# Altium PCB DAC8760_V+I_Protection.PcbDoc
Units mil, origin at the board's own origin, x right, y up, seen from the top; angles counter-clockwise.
Board outline 3000 x 3000 mil, 4 copper layers (Top Layer, Mid-Layer 1, Mid-Layer 2, Bottom Layer); 47 components, 28 nets, 152 pads, 114 vias.
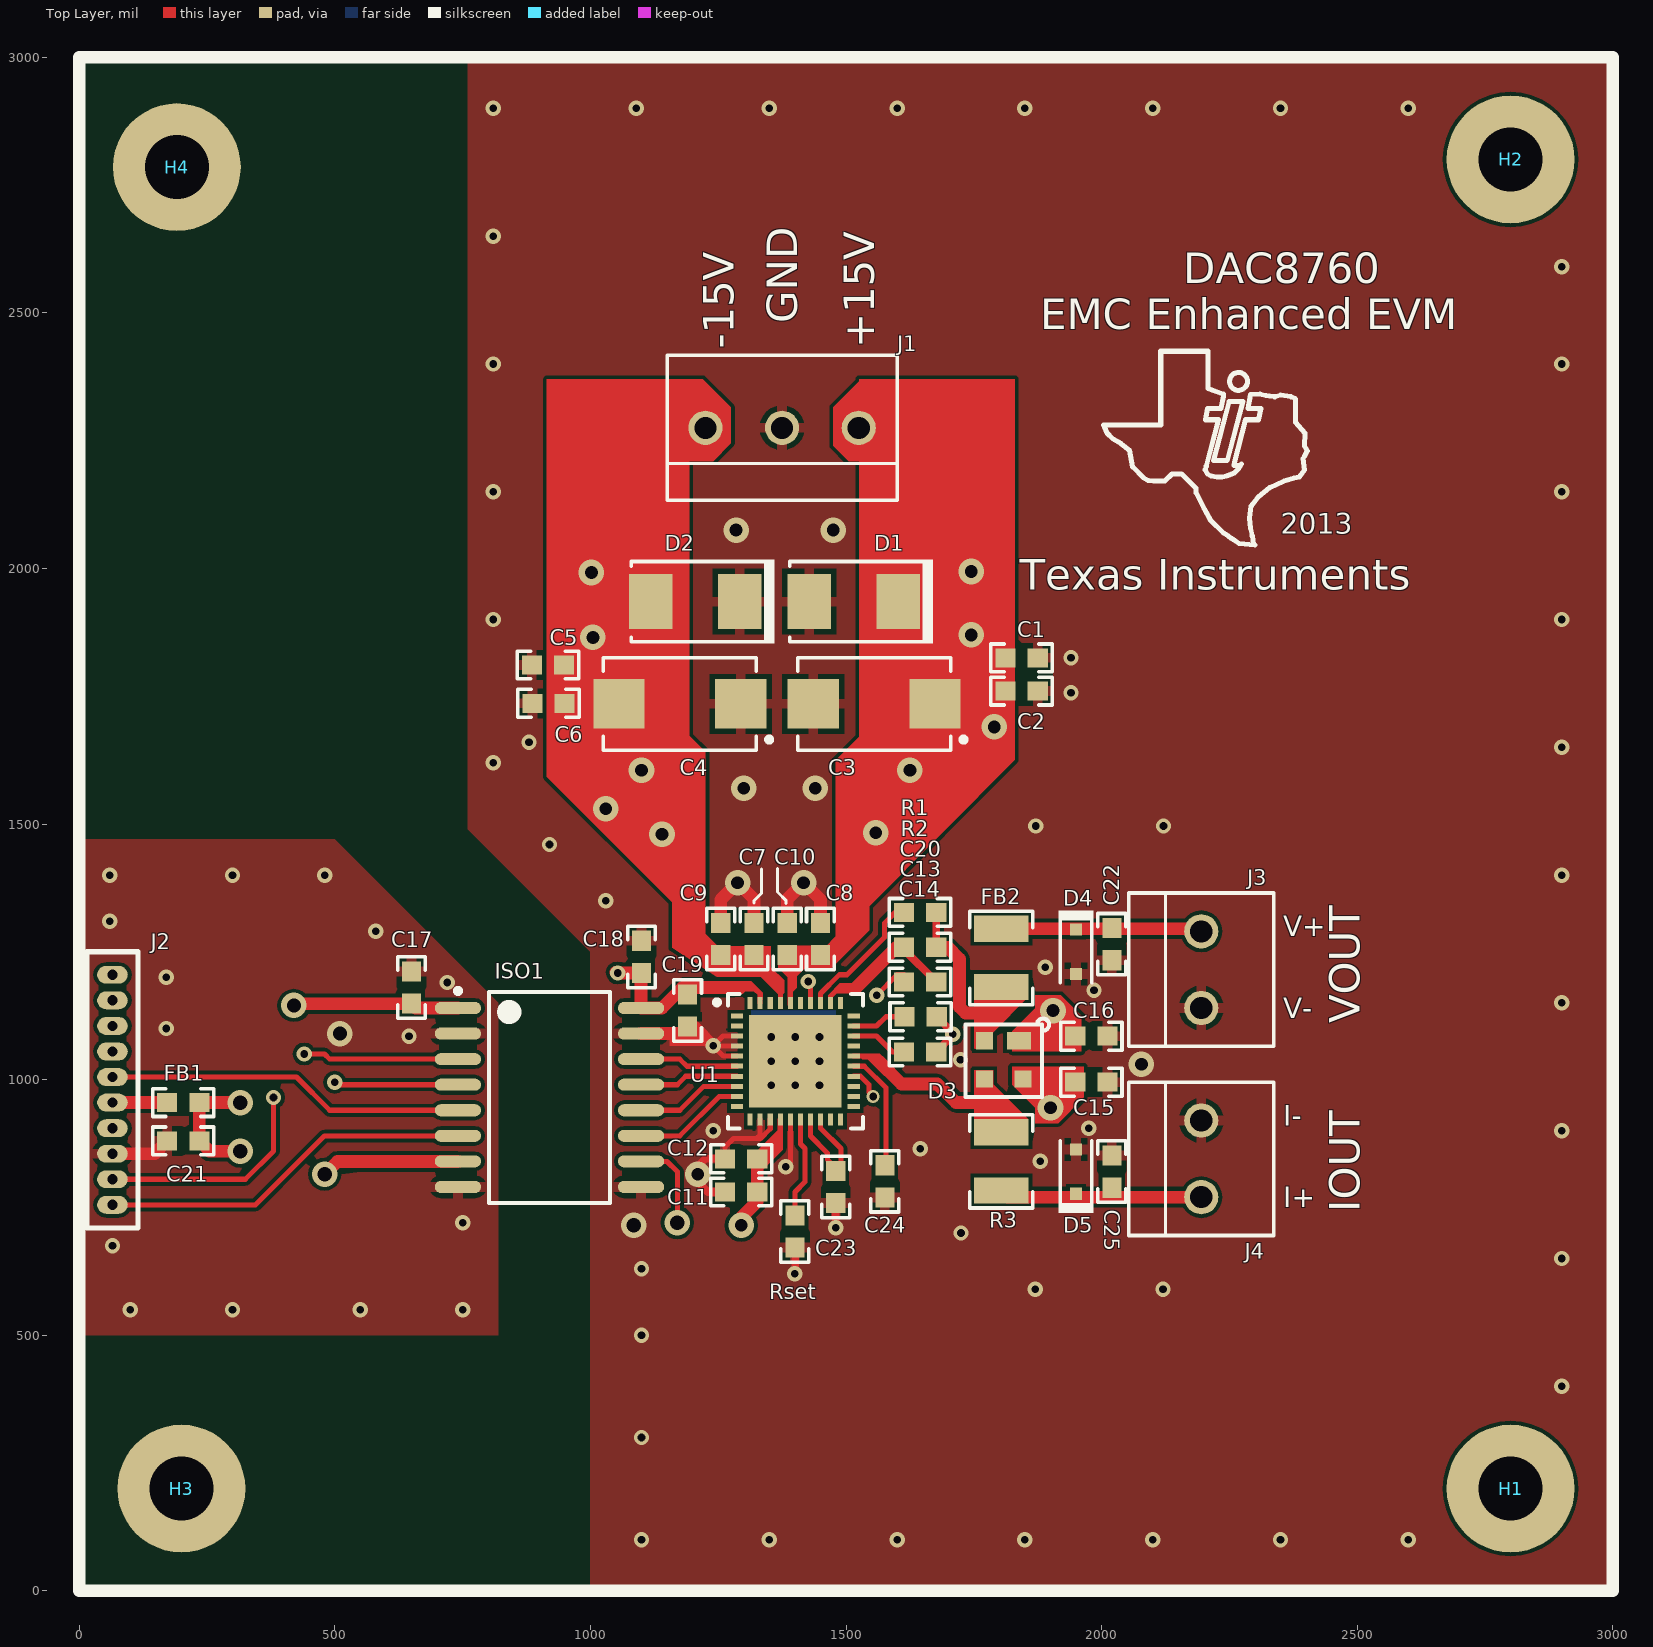
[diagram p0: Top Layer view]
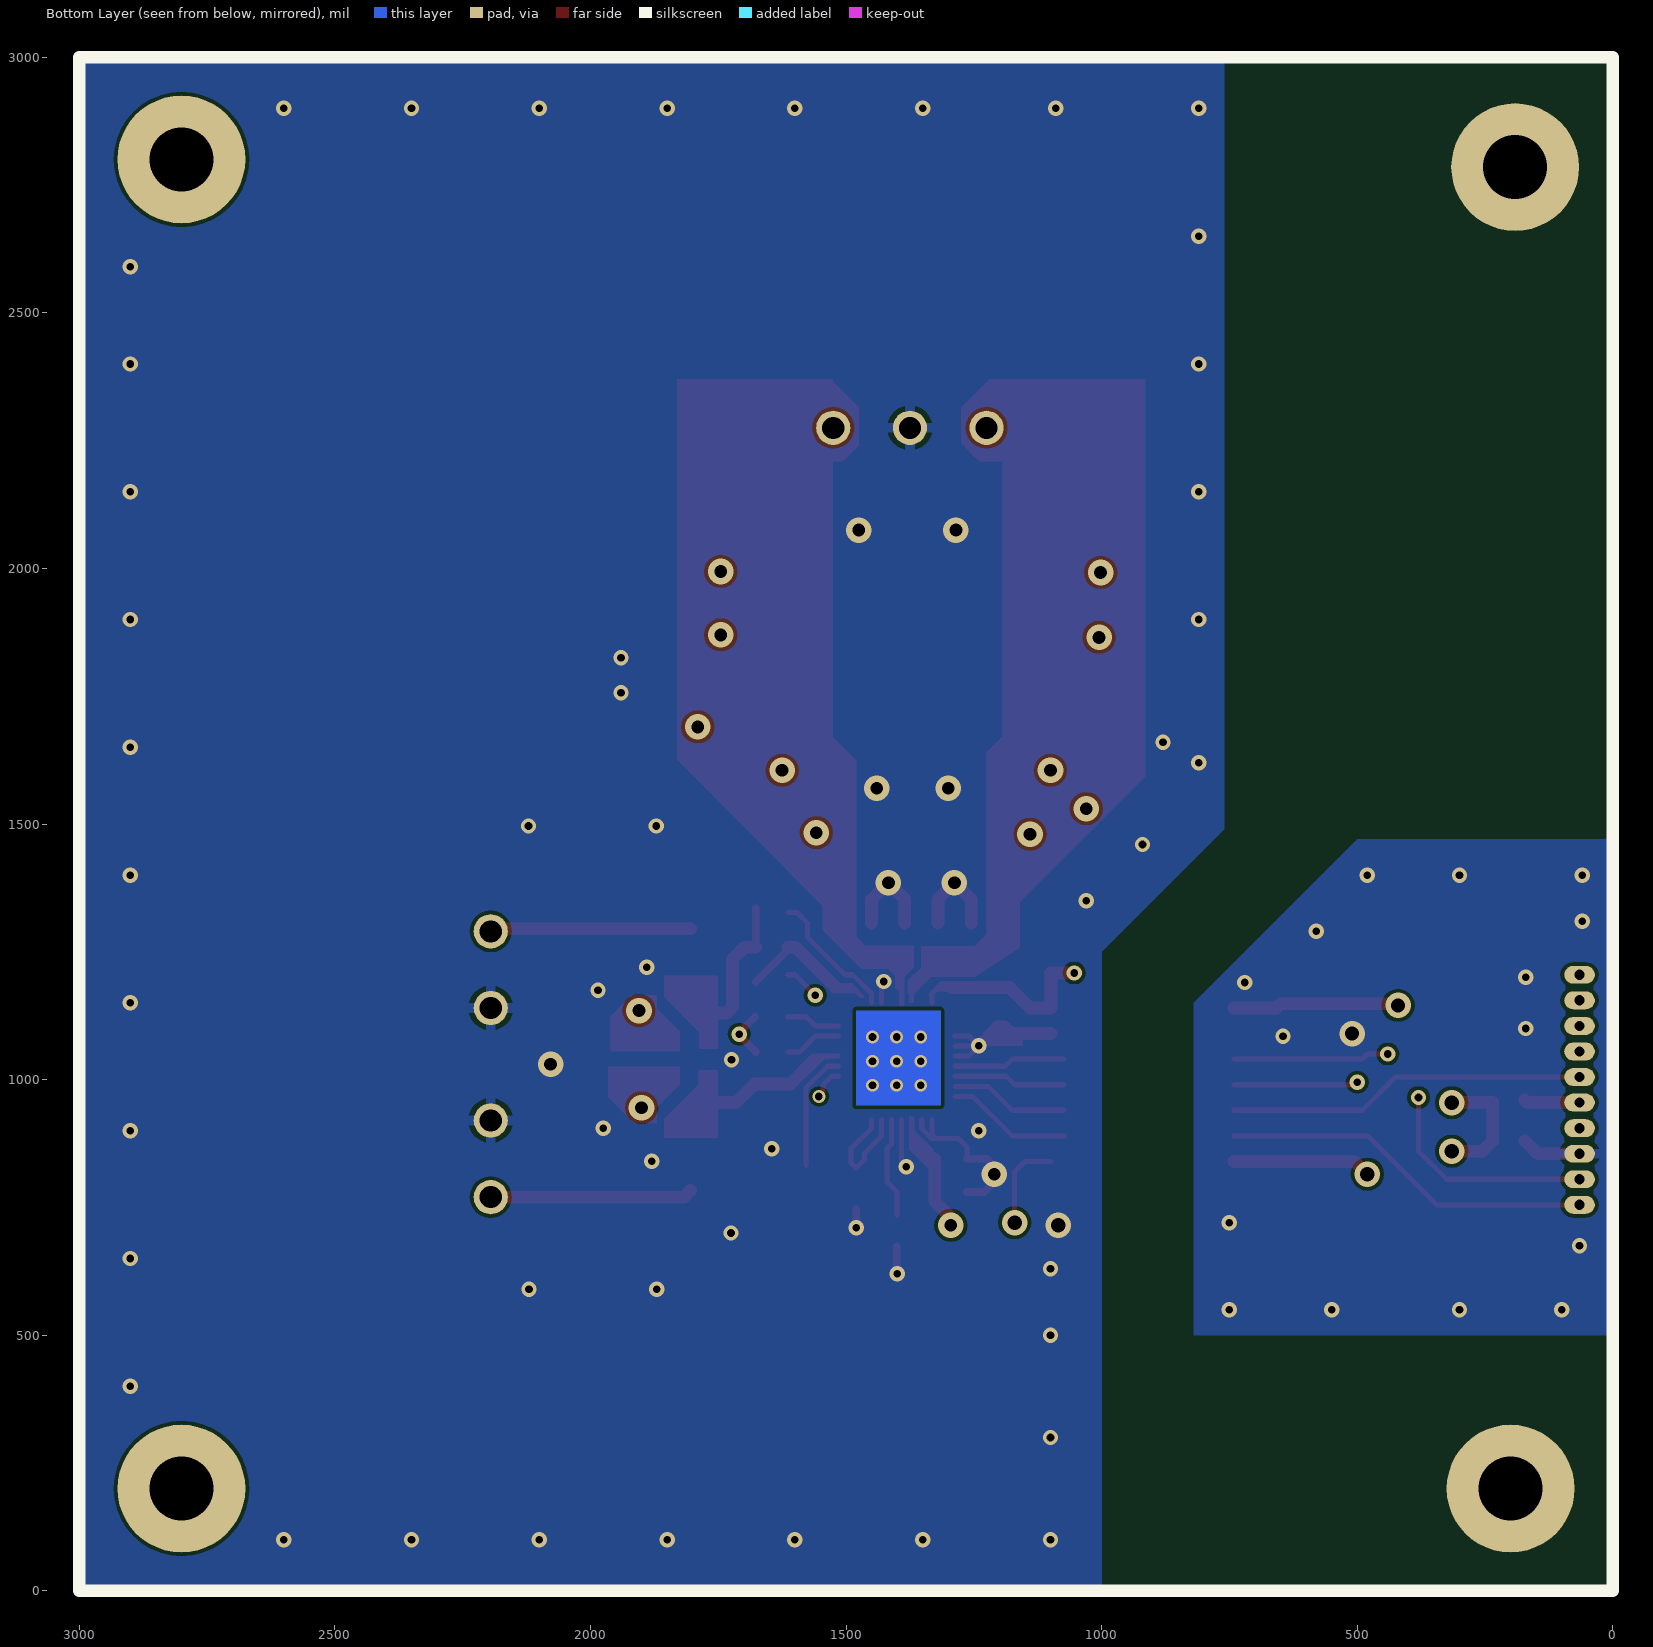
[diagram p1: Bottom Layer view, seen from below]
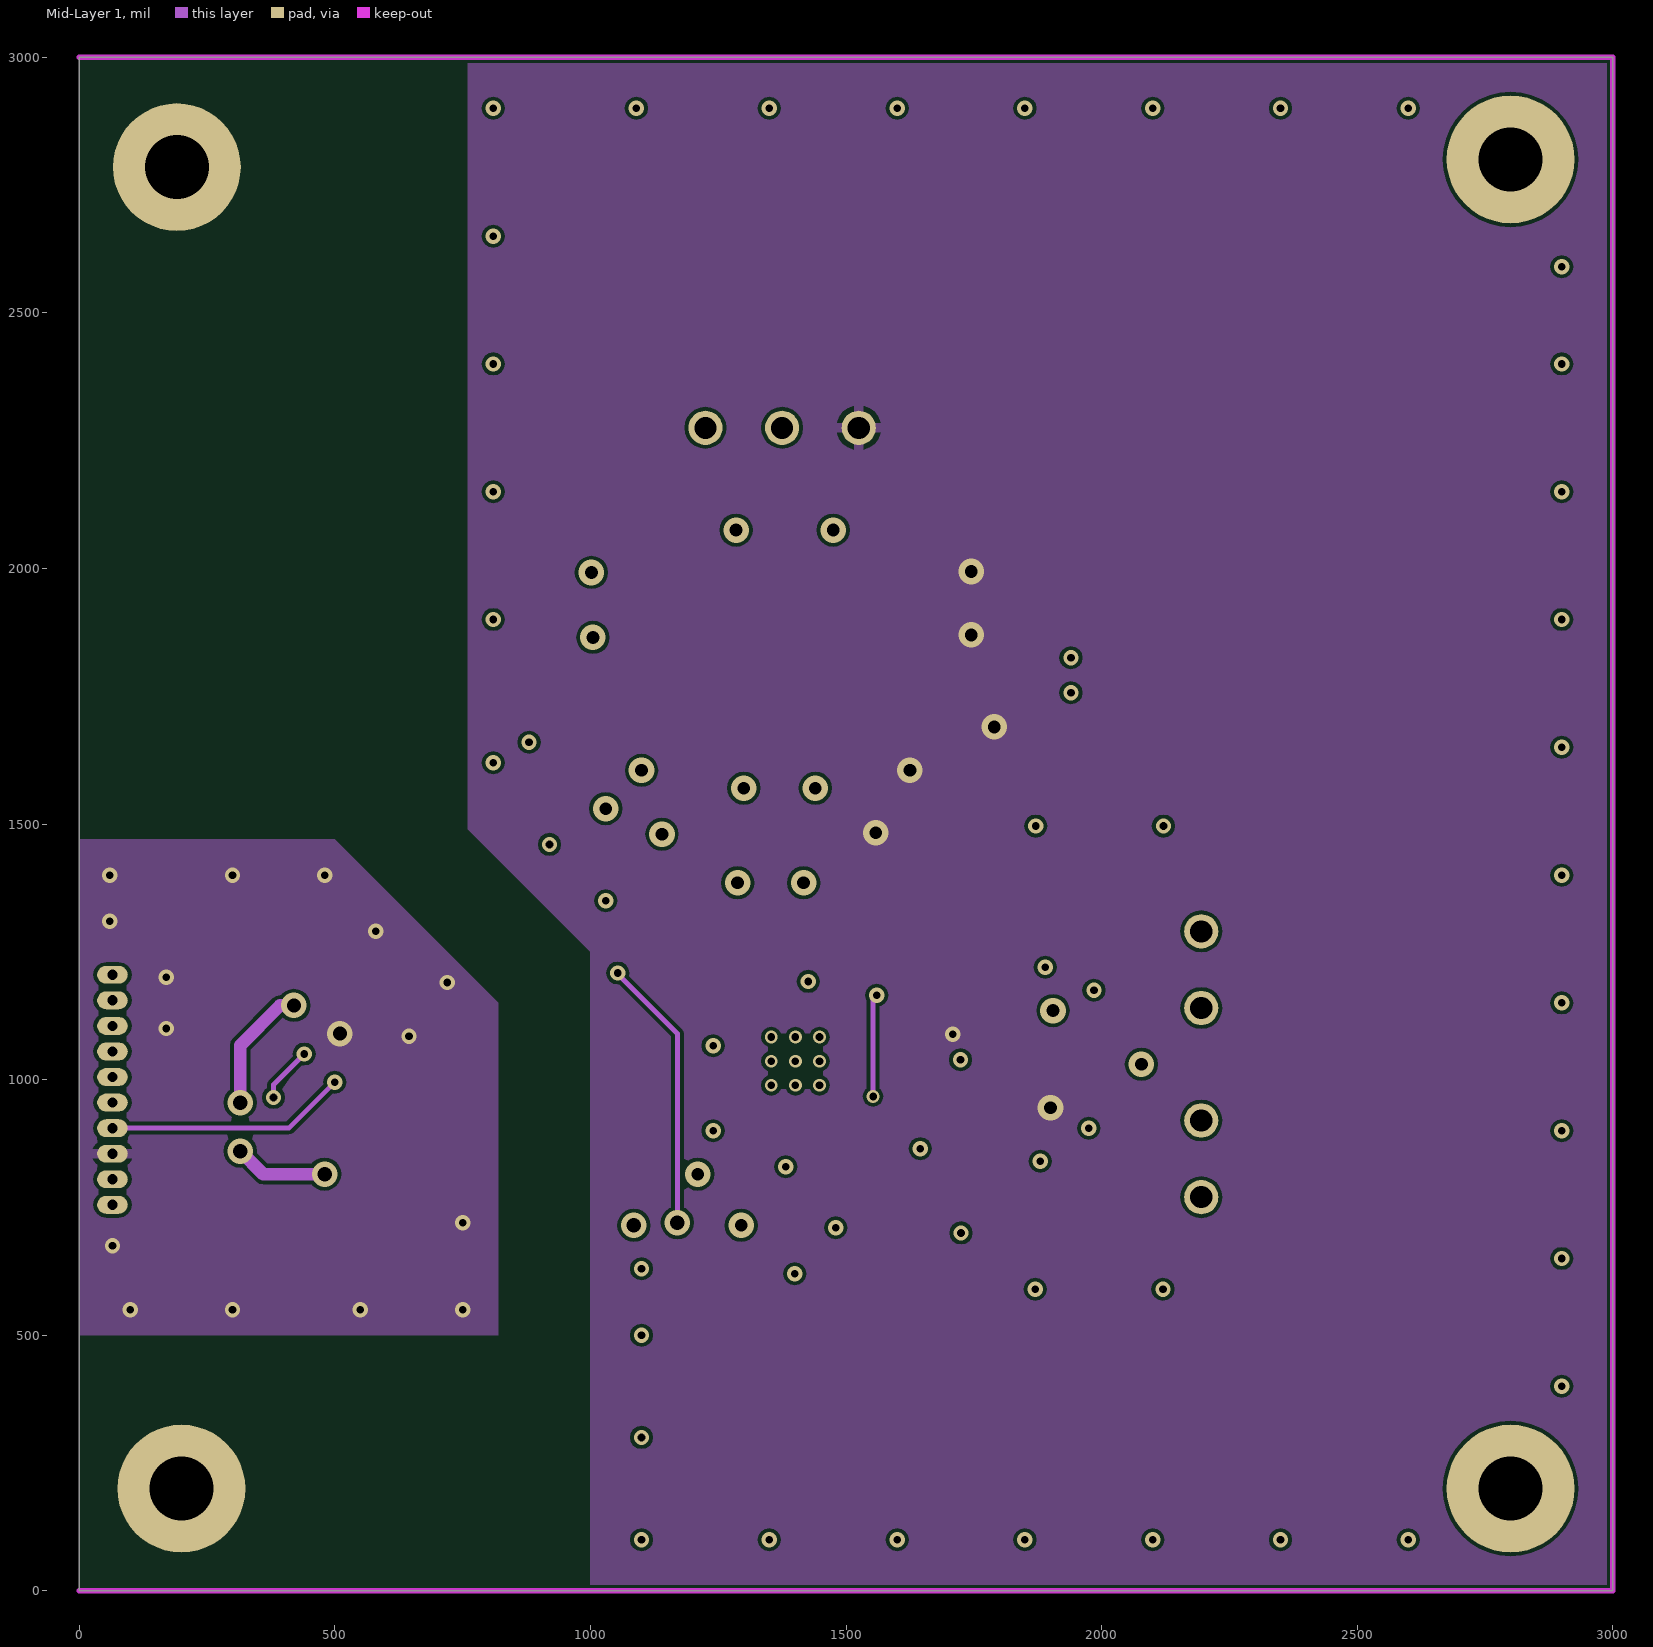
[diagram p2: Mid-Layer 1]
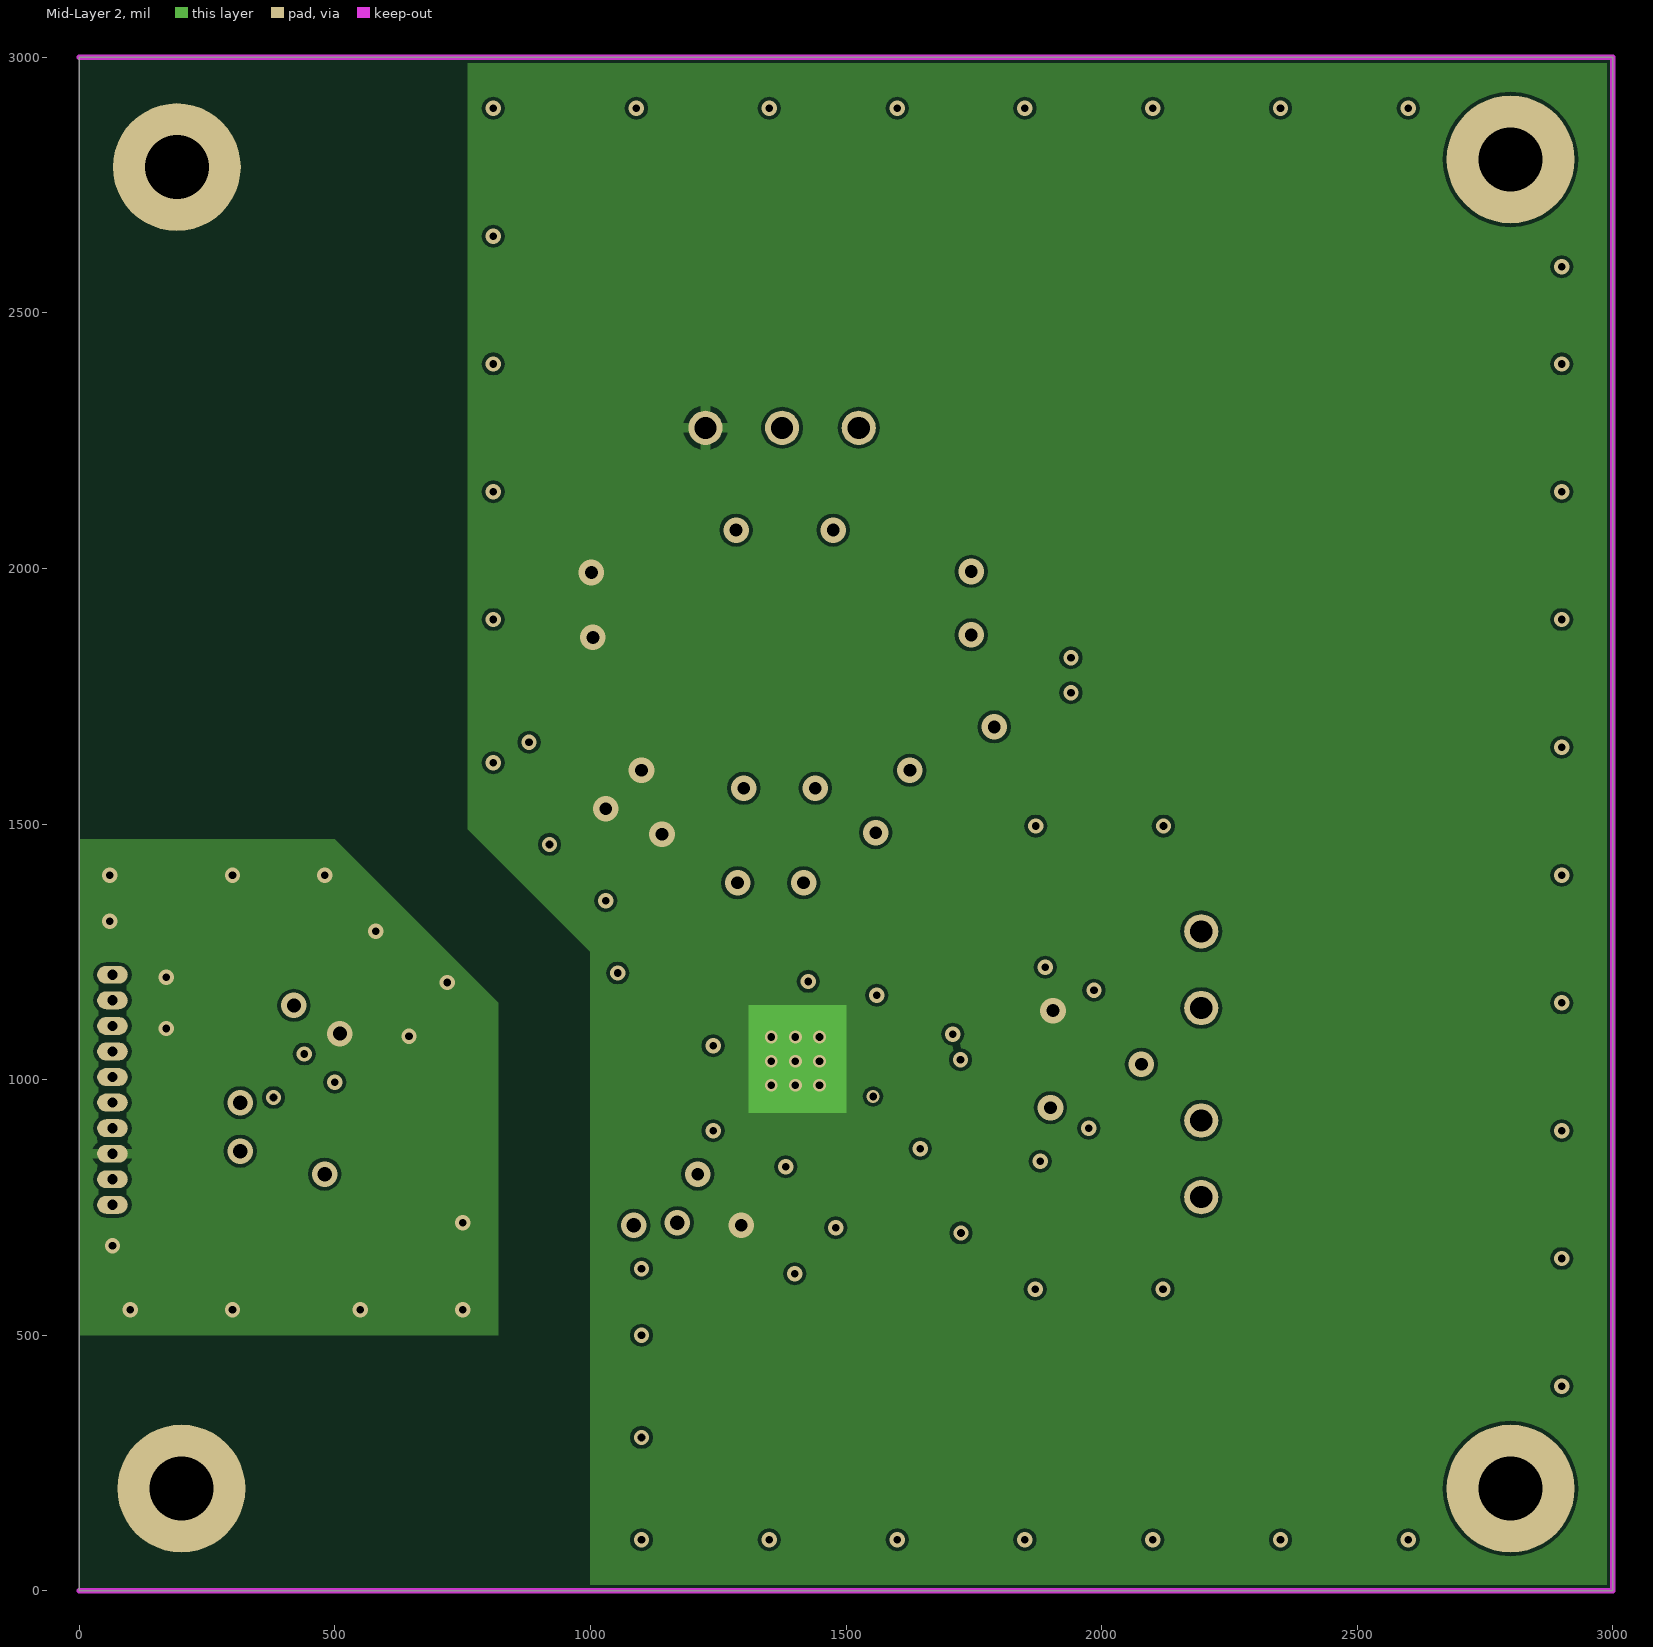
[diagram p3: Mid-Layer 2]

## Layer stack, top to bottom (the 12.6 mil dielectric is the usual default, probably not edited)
Top Layer: signal copper 1.4
Dielectric: core 12.6, FR-4, Dk 4.8
Mid-Layer 1: signal copper 1.4
Dielectric: prepreg 12.6, FR-4, Dk 4.8
Mid-Layer 2: signal copper 1.4
Dielectric: core 12.6, FR-4, Dk 4.8
Bottom Layer: signal copper 1.4

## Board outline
0,0 3000,0 3000,3000 0,3000

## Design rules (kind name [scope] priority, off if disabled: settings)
Clearance [All] p1: gap=6
HoleSize [All] p1: absolutevalues=TRUE maxlimit=146 minlimit=1 maxpercent=80.000 minpercent=20.000
HoleToHoleClearance [All] p1: gap=0 allowstackedmicrovias=TRUE
MinimumSolderMaskSliver [All] p1: minsoldermaskwidth=0
PolygonConnect PolygonConnect_1 [(InComponentClass('All Components'))] p1: connectstyle=Relief reliefconductorwidth=20 reliefentries=4 polygonreliefangle="90 Angle" airgapwidth=10
PolygonConnect [All] p2: connectstyle=Direct reliefconductorwidth=20 reliefentries=4 polygonreliefangle="90 Angle" airgapwidth=10
RoutingVias [All] p1: holewidth=15 width=30 viastyle="Through Hole" minholewidth=15 minwidth=30 maxholewidth=28 maxwidth=50
SilkToSilkClearance [All] p1 off: silktosilkclearance=10
SilkscreenOverComponentPads [All] p1 off: minsilkscreentomaskgap=10
SolderMaskExpansion [All] p1: expansion=4
Width [All] p1: maxlimit=200 minlimit=10 preferedwidth=10
23 further rules are at their usual default settings.

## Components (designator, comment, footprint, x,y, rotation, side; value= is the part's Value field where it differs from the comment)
C1 "GRM188R71H104KA93D" 0603 1843.5,1825 r180 top
C2 "06035A101JAT2A" 0603 1843.5,1760 r0 top
C3 "293D106X9050E2TE3" 7343-43 1555,1735 r180 top
C4 "293D106X9050E2TE3" 7343-43 1175,1735 r180 top
C5 "GRM188R71H104KA93D" 0603 917,1811 r180 top
C6 "06035A101JAT2A" 0603 918,1736 r0 top
C7 "06035A101JAT2A" 0603 1320,1275 r270 top
C8 "06035A101JAT2A" 0603 1450,1275 r90 top
C9 "GRM188R71H104KA93D" 0603 1255,1275 r270 top
C10 "GRM188R71H104KA93D" 0603 1385,1275 r90 top
C11 "06035A101JAT2A" 0603 1295,780 r0 top
C12 "GRM188R71H104KA93D" 0603 1295,845 r0 top
C13 "GRM188R72A102KA01D" 0603 1646,1123 r180 top
C14 "GRM188R72A102KA01D" 0603 1645,1054 r180 top
C15 "GRM188R71H104KA93D" 0603 1980,995 r0 top
C16 "GRM188R71H104KA93D" 0603 1980,1085 r0 top
C17 "GRM188R71H104KA93D" 0603 650,1180 r90 top
C18 "GRM188R71H104KA93D" 0603 1100,1240 r90 top
C19 "GRM188R71H104KA93D" 0603 1190,1135 r270 top
C20 "GRM1885C1H222JA01D" 0603 1645,1191 r180 top
C21 "GRM188R71H104KA93D" 0603 203.5,880 r180 top
C22 "06035C104KAT2A" 0603 2020,1265 r270 top
C23 "06035C104KAT2A" 0603 1480,790 r270 top
C24 "C1608X7R1H223K" 0603 1576,801 r270 top
C25 "06035C104KAT2A" 0603 2020,820 r90 top
D1 "SMBJ15A-13-F" SMB 1515,1935 r180 top
D2 "SMBJ15A-13-F" SMB 1205,1935 r180 top
D3 "CD143A-SR70" SOT-143 1846,1076 r270 top
D4 "CDSOD323-T15SC" sod-323 1950,1250 r270 top
D5 "CDSOD323-T15SC" sod-323 1950,820 r90 top
FB1 "BLM18HG601SN1D" 0603 203.5,955 r0 top
FB2 "MH3261-501Y" 1210 1804,1238 r90 top
H1 "NA" "Mounting Hole" 2800,200 r0 top
H2 "NA" "Mounting Hole" 2800,2800 r0 top
H3 "NA" "Mounting Hole" 200,200 r0 top
H4 "NA" "Mounting Hole" 191,2785 r0 top
ISO1 "ISO7641FCDW" M16B_N 920,965 r0 top
J1 "ED555/3DS" ED555/3DS 1225,2275 r0 top
J2 "851-43-050-20-001000" 851-43-010-20-001000 65,980 r0 top
J3 "V+I" ED555/2DS 2195,1290 r270 top
J4 "IOUT" ED555/2DS 2195,920 r270 top
R1 "CRCW060315R0JNEA" 0603 1645,1327 r0 top
R2 "CRCW060315R0JNEA" 0603 1645,1259 r0 top
R3 "RPC2512JT15R0" 1210 1804,840 r270 top
Rset "RT0603BRD0715KL" 0603 1400,702.99 r90 top
TI1 "Texas Instruments logo" "TI LOGO" 8500,6348 r0 top
U1 "DAC8760" SQA40A 1401,1036 r0 top

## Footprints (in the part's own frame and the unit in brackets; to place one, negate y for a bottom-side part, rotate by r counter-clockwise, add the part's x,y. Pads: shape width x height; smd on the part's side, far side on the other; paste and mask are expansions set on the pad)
0603 [mm] "0603 from SM-752 data"
  rect 1x0.95 smd: 1(-0.8,0) 2(0.8,0)
  silkscreen extent -1.52,-0.69 1.52,0.69, body extent -0.87,-0.47 0.87,0.47, height 0.85
851-43-010-20-001000 [mil] "Female 10 Pin connector for SM-USB-DIG"
  oval 60x35 hole 20: 1(0,225) 2(0,175) 3(0,125) 4(0,75) 5(0,25) 6(0,-25) 7(0,-75) 8(0,-125) 9(0,-175) 10(0,-225)
  silkscreen extent -50,-270 50,270, body extent -210,-257 8,257, height 87
1210 [mm] "1210 from SM-752 data"
  rect 1.3x2.7 smd: 1(-1.45,0) 2(1.45,0)
  silkscreen extent -2.32,-1.57 2.32,1.57, body extent -1.7,-1.35 1.7,1.35, height 1.35
7343-43 [mm] "Medium density IPC based on Kemet T495 series"
  rect 2.55x2.45 smd: 1(-3.025,0) 2(3.025,0)
  silkscreen extent -4.56,-2.3 3.8,2.3, body extent -3.8,-2.3 3.8,2.3, height 4.3
ED555/2DS [mm] "TERMINAL BLOCK 3.5MM 2POS PCB"
  round 1.7 hole 1.1: 1(0,0) 2(3.81,0)
  silkscreen extent -1.91,-3.6 5.72,3.6, body extent -1.9,-3.6 5.72,3.7, height 8.52
ED555/3DS [mm] "TERMINAL BLOCK 3.5MM 3POS PCB"
  round 1.7 hole 1.1: 1(0,0) 2(3.81,0) 3(7.62,0)
  silkscreen extent -1.91,-3.6 9.53,3.6, body extent -1.91,-3.7 9.53,3.6, height 6.35
M16B_N [mm] "SOIC, 16-Leads, Body 10.3x7.5mm, Pitch 1.27mm, IPC Medium Density"
  oval 2.3x0.6 smd: 1(-4.55,4.445) 2(-4.55,3.175) 3(-4.55,1.905) 4(-4.55,0.635) 5(-4.55,-0.635) 6(-4.55,-1.905) 7(-4.55,-3.175) 8(-4.55,-4.445) 9(4.55,-4.445) 10(4.55,-3.175) 11(4.55,-1.905) 12(4.55,-0.635) 13(4.55,0.635) 14(4.55,1.905) 15(4.55,3.175) 16(4.55,4.445)
  silkscreen extent -4.67,-5.25 3,5.42, body extent -3.75,-5.25 3.75,5.25, height 2.65
"Mounting Hole" [mil]
  round 250 hole 125: 1(0,0)
SMB [mil] "Molded Diode, 2-Leads, Body 5.4x3.6mm, IPC Medium Density, based on OnSemi component dimensions"
  rect 85x107.99 smd: 1(-87.01,0) 2(87.01,0)
  silkscreen extent -155,-82 125,82, body extent -106,-71 106,71, height 91
sod-323 [mm] "NXP recommended land pattern"
  rect 0.6x0.6 smd paste-0.05: 1(-1.1,0) 2(1.1,0)
  silkscreen extent -2.06,-0.86 1.53,0.86, body extent -1.3,-0.67 1.3,0.68, height 1.1
SOT-143 [mm]
  rect 0.85x1.2 smd: 1(0,-0.2)
  rect 0.85x0.85 smd: 2(0,-1.9) 3(1.9,-1.9) 4(1.9,0)
  silkscreen extent -1.1,-2.85 2.8,1.3, body extent -0.26,-2.41 2.16,0.51, height 1
SQA40A [mm] "QFN, 40-Leads, Body 6x6mm, Pitch 0.5mm, NSC Recommended"
  rect 0.6x0.25 smd paste-0.125 mask+0.051: 1(-2.9,2.25) 2(-2.9,1.75) 3(-2.9,1.25) 4(-2.9,0.75) 5(-2.9,0.25) 6(-2.9,-0.25) 7(-2.9,-0.75) 8(-2.9,-1.25) 9(-2.9,-1.75) 10(-2.9,-2.25) 21(2.9,-2.25) 22(2.9,-1.75) 23(2.9,-1.25) 24(2.9,-0.75) 25(2.9,-0.25) 26(2.9,0.25) 27(2.9,0.75) 28(2.9,1.25) 29(2.9,1.75) 30(2.9,2.25)
  rect 0.25x0.6 smd paste-0.125 mask+0.051: 11(-2.25,-2.9) 12(-1.75,-2.9) 13(-1.25,-2.9) 14(-0.75,-2.9) 15(-0.25,-2.9) 16(0.25,-2.9) 17(0.75,-2.9) 18(1.25,-2.9) 19(1.75,-2.9) 20(2.25,-2.9) 31(2.25,2.9) 32(1.75,2.9) 33(1.25,2.9) 34(0.75,2.9) 35(0.25,2.9) 36(-0.25,2.9) 37(-0.75,2.9) 38(-1.25,2.9) 39(-1.75,2.9) 40(-2.25,2.9)
  rect 4.6x4.6 smd paste-2.3 mask+0.051: 41(0,0)
  silkscreen extent -4.02,-3.35 3.35,3.35, body extent -3.05,-3.05 3.05,3.05, height 0.8
"TI LOGO" [mil] "TI BUG"
  silkscreen extent -6496,-4302 -6097,-3923

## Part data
C1 C5 C9 C10 C12 C15 C16 C17 C18 C19 C21 C22 C23 C25: "CAP, CERM, 0.1uF, 50V, +/-10%, X7R, 0603"
C2 C6 C7 C8 C11: "CAP, CERM, 100pF, 50V, +/-5%, C0G/NP0, 0603"
C3 C4: "CAP, TANT, 10uF, 50V, +/-10%, 0.8 ohm, 7343-43 SMD"
C13 C14: "CAP, CERM, 1000pF, 100V, +/-10%, X7R, 0603"
C20: "CAP, CERM, 2200pF, 50V, +/-5%, C0G/NP0, 0603"
C24: "CAP, CERM, 0.022uF, 50V, +/-10%, X7R, 0603"
D1 D2: "Diode, TVS, Uni, 15V, 600W, SMB"
D3: "IC TVS ARRAY 2-LINE 70V SOT-143"
D4 D5: library part SMAJ15CA, "DIODE TVS ARRAY 15V SOD323"
FB1: library part Ferrite_Bead, "FERRITE CHIP 600 OHM 200MA 0603"
FB2: library part Ferrite_Bead, "BEAD FERRITE 500 OHM 3.0A 3216"
H1 H2 H3 H4: library part "Mounting Hole", "Mounting Hole"
ISO1: library part ISO7241, "ISOLATOR DGTL 25MBPS 4CH 16SOIC"
J1: library part 1715734, "TERMINAL BLOCK 3.5MM 3POS PCB"
J2: library part SM-USB-DIG-CONN, "CONN SOCKET 50PIN .050 R/A SNGL"
J3 J4: library part 1727010, "TERMINAL BLOCK 3.5MM 2POS PCB"
R1 R2: "RES, 15 ohm, 5%, 0.1W, 0603"
R3: library part CRA2512-FZ-R080ELF, "RES 15 OHM 1W 5% 2512"
Rset: "RES, 15.0k ohm, 0.1%, 0.1W, 0603"
TI1: library part "TI LOGO", "TI BUG"
U1: "DAC8760 DAC-XTR RTA QFN-40"

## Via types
v1: diameter 30, hole 15, Top Layer to Bottom Layer, 76 vias
v2: diameter 50, hole 25, Top Layer to Bottom Layer, 21 vias
v3: diameter 25, hole 15, Top Layer to Bottom Layer, 10 vias
v4: diameter 50, hole 28, Top Layer to Bottom Layer, 7 vias

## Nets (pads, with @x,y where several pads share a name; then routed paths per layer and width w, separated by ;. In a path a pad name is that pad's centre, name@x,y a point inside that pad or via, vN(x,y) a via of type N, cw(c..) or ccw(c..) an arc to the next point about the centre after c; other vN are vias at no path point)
+15VB: C1.2 C2.1 C3.1 C8.1 C10.1 C13.1 C14.1 C15.1 D1.1 D3.4 J1.3 U1.36 | length 504.2
  Top Layer w15: C14.1 1709,1086.5 v1(1709,1089) 1709,1091.5 C13.1
  Top Layer w25: C8.1 1478.5,1243.5 1505,1270 ; D3.4 1928.72,1001.2 C15.1@1937.46,992.46 ; C15.1@1940,985 C15.1@1940,995
  Top Layer w50: J1.3@1541,2291 1778.68,2291
  other v2: 1900,945 1558,1483 1625,1605 1790,1690 1745,1870 1745,1994
-15VB: C4.2 C5.1 C6.2 C7.2 C9.2 C11.2 C12.2 C16.1 D2.2 D3.1 J1.1 U1.14 U1.37 U1.41 | length 551.3
  Top Layer w10: C12.2 1350,845 1371.47,866.47 U1.14
  Top Layer w25: D2.2@1116.39,1943.4 D2.2@1116.39,1948.6 ; 1195,1345 1195,1275 1226.5,1243.5 C9.2 ; v2(1295,715) 1295,730 1326.5,761.5 C11.2 C12.2 ; D3.1 1928.91,1076 C16.1@1943.91,1091
  Top Layer w50: D2.2@1091.59,1918.6 1116.39,1943.4 D2.2@1118.99,1946
  other v2: 1905,1135 1140,1480 1030,1530 1100,1605 1005,1865 1002,1992
  other v3: 1353.76,988.76 1401,988.76 1448.24,988.76 1353.76,1036 1401,1036 1448.24,1036 1353.76,1083.24 1401,1083.24 1448.24,1083.24
\C\S_AO: ISO1.14 U1.6 | length 218.4
  Top Layer w10: ISO1.14@1074.13,1040 1175,1040 1188.84,1026.16 U1.6
\C\S_DIG: ISO1.3 J2.9 | length 857.6
  Top Layer w10: J2.9 325,805 380,860 v1(380,965) ; v1(440,1050) 480,1050 490,1040 ISO1.3
  Mid-Layer 1 w10: v1(380,965) 380,990 v1(440,1050)
DGND: C17.2 C21.2 ISO1.2 ISO1.8 J2.8 | length 117.4
  Top Layer w25: J2.8 147.01,855 C21.2
  other v1: 100,550 300,550 550,550 750,550 65,675 750,720 645,1085 170,1100 720,1190 170,1200 580,1290 60,1310 60,1400 300,1400 480,1400
  other v4: 510,1090
GNDB: C1.1 C2.2 C3.2 C4.1 C5.2 C6.1 C7.1 C8.2 C9.1 C10.2 C11.1 C12.1 C15.2 C16.2 C18.2 C19.2 C22.2 C23.2 C24.2 C25.2 D1.2 D2.1 D4.2 D5.2 ISO1.9 ISO1.15 J1.2 J3.2 J4.1 Rset.1 U1.3 U1.4 U1.5 U1.12 U1.13 U1.15 U1.34 | length 1304.3
  Top Layer w10: C12.1 1263.5,868.5 1280,885 1325,885 ; U1.5 1260.16,1045.84 v1(1240,1066) ; U1.4 1256.47,1065.53 1256,1066 v1(1240,1066) ; U1.3 1259.21,1085.21 v1(1240,1066) ; U1.12 1332.1,892.1 1325,885 ; U1.13 1351.79,903.76 1333.03,885 1325,885 ; v1@1376,823.5 v1(1382,829.5) 1391.16,838.66 U1.15 ; v1(1426,1192) 1422,1196 1430,1196 1433,1193 1430.53,1190.53 U1.34
  Top Layer w15: C11.1 1230,780 1195,815 1225,845 C12.1 ; v1(1400,620) 1401,621 Rset.1@1401,674 ; v1(1480,710) C23.2@1480,747
  Top Layer w25: ISO1.15 1176.5,1090 C19.2 1202.5,1103.5 v1(1240,1066) ; C9.1 1255,1352 v2(1288,1385) 1320,1353 C7.1 ; C10.2 1385,1353 v2(1417,1385) 1450,1352 C8.2
  Bottom Layer w25: J4.1@2183.5,920 J4.1
  other v1: 1100,100 1350,100 1600,100 1850,100 2100,100 2350,100 2600,100 1100,300 2900,400 1100,500 1870,590 2120,590 1100,630 2900,650 1725,700 1880,840 1645,865 1240,900 2900,900 1975,905 1724,1039 2900,1150 1985,1175 1890,1220 1030,1350 2900,1400 920,1460 1871,1496 2121,1496 810,1620 2900,1650 880,1660 1940,1757 1940,1825 810,1900 2900,1900 810,2150 2900,2150 810,2400 2900,2400 2900,2590 810,2650 810,2900 1090,2900 1350,2900 1600,2900 1850,2900 2100,2900 2350,2900 2600,2900
  other v2: 1210,815 2078,1030 1300,1570 1440,1570 1285,2075 1475,2075
  other v4: 1085,715
GPIO4: J2.2
MISO_AO: ISO1.11 U1.9 | length 244.6
  Top Layer w10: ISO1.11@1074.13,890 1175,890 1252.1,967.1 U1.9
MISO_DIG: ISO1.6 J2.10 | length 731.8
  Top Layer w10: J2.10 345,755 480,890 ISO1.6
MOSI_AO: ISO1.12 U1.8 | length 232.1
  Top Layer w10: ISO1.12@1074.13,940 1175,940 1221.79,986.79 U1.8
MOSI_DIG: ISO1.5 J2.5 | length 702.8
  Top Layer w10: J2.5 425,1005 490,940 ISO1.5
NetC13_2: C13.2 U1.29 | length 106.8
  Top Layer w10: U1.29 1559.9,1104.9 1578,1123 C13.2
NetC14_2: C14.2 U1.28 | length 111.3
  Top Layer w10: U1.28 1559.79,1085.21 1591,1054 C14.2
NetC18_1: C18.1 C19.1 ISO1.10 ISO1.16 U1.39 | length 1119.1
  Top Layer w10: ISO1.10 1150,840 1170,820 v4(1170,720) ; 1280,1180 1320,1180 1332.1,1167.9 U1.39
  Top Layer w25: v1(1053.62,1208.5) v1@1051.5,1208.5 ; 1280,1180 1180,1180 1140,1140 ISO1.16 1099.13,1207.64 C18.1 v1@1051.5,1208.5 ; v1@1051.5,1208.5 1050,1210 v1@1051.5,1208.5
  Mid-Layer 1 w10: v1(1053.62,1208.5) 1051.5,1208.5 1050,1210 1170,1090 v4(1170,720)
NetC20_1: C20.1 R2.1 U1.32 | length 213.2
  Top Layer w15: R2.1 1613.5,1253.99 C20.1
  Top Layer w25: 1525,1185 1599,1259 R2.1
NetC20_2: C20.2 U1.24 | length 333.9
  Top Layer w10: U1.24 1528.53,1006.47 1545,990 1545,975 v3(1553,967) ; v1(1560,1165) 1600,1205 C20.2@1613.5,1205
  Mid-Layer 1 w10: v3(1553,967) 1553,1158 v1(1560,1165)
NetC22_1: C22.1 D4.1 FB2.2 J3.1 | length 410.6
  Top Layer w25: FB2.2 2189.91,1295.09 J3.1
  Bottom Layer w25: J3.1@2177.5,1290 J3.1
NetC23_1: C23.1 U1.17 U1.18 | length 230.8
  Top Layer w10: U1.17 1430.53,889.47 1463.5,856.5 1463.5,843.5 1480,827 1490,837 1490,865 1450.21,904.79 U1.18
NetC24_1: C24.1 U1.25 | length 231.8
  Top Layer w10: U1.25 1535.84,1026.16 1578,984 C24.1@1578,832.5
NetC25_1: C25.1 D5.1 J4.2 R3.2 | length 417.8
  Top Layer w25: R3.2 1816.91,770 J4.2
  Bottom Layer w25: J4.2@2173.5,770 J4.2
NetD3_2: D3.2 FB2.1 R1.2 R2.2 | length 272.6
  Top Layer w15: R2.2@1676.5,1270 R1.2 R1.2@1676.5,1335
  Top Layer w25: R2.2 1699,1259 1722,1236 1722,1142 1734,1130 1770,1130 1771,1129 ; FB2.1@1767.06,1165 FB2.1@1770,1167.94
NetD3_3: D3.3 R3.1 U1.26 | length 306.6
  Top Layer w10: U1.26 1559,1045.84
  Top Layer w25: 1565.25,1034.75 1608.5,991.5 1645,991.5 1678.5,991.5 1715,955 1795,955
NetFB1_1: FB1.1 J2.6 | length 109.1
  Top Layer w25: J2.6 167.01,955 FB1.1@172.01,960
NetR1_1: R1.1 U1.33 | length 263.5
  Top Layer w10: U1.33 1450.21,1168.21 1487,1205 1502,1205 1575,1278 1575,1306 1596,1327 R1.1
NetRset_2: Rset.2 U1.16 | length 199.4
  Top Layer w10: Rset.2 1400,780 1420,800 1420,865 1410.84,874.16 U1.16
SCLK_AO: ISO1.13 U1.7 | length 219.5
  Top Layer w10: ISO1.13@1074.13,990 1170,990 1186.47,1006.47 U1.7
SCLK_DIG: ISO1.4 J2.7 | length 720.2
  Top Layer w10: v1@495,995 500,990 ISO1.4
  Mid-Layer 1 w10: J2.7 410,905 v1(500,995)
VDUT: C17.1 C21.1 FB1.2 ISO1.1 ISO1.7 | length 1313.3
  Top Layer w25: 235,915 FB1.2 ; v4(315,860) 255,860 C21.1 FB1.2 ; v4(315,955) FB1.2 ; v4(420,1145) 423.5,1148.5 C17.1 658.5,1140 ISO1.1 ; v4(480,815) 505,840 ISO1.7
  Mid-Layer 1 w25: v4(315,860) 360,815 v4(480,815) ; v4(315,955) 315,1067 393,1145 v4(420,1145)
pads on no net: H1.1 H2.1 H3.1 H4.1 J2.1 J2.3 J2.4 U1.1 U1.2 U1.10 U1.11 U1.19 U1.20 U1.21 U1.22 U1.23 U1.27 U1.30 U1.31 U1.35 U1.38 U1.40

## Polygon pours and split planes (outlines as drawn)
-15VB on Mid-Layer 2 "Top Layer-No Net" (solid, remove dead copper, pour order 13): 760,3000 760,1490 1000,1250 1000,1140 1000,0 3000,0 3000,3000
DGND on Mid-Layer 2 "Top Layer-No Net 2" (solid, remove dead copper, pour order 9): 0,1470 500,1470 610,1360 820,1150 820,856.78 820,500 0,500
+15VB on Mid-Layer 1 "Top Layer-No Net" (solid, remove dead copper, pour order 14): 760,3000 760,1490 1000,1250 1000,1140 1000,0 3000,0 3000,3000
DGND on Mid-Layer 1 "Top Layer-No Net 2" (solid, remove dead copper, pour order 10): 0,1470 500,1470 610,1360 820,1150 820,856.78 820,500 0,500
GNDB on Bottom Layer "Top Layer-No Net" (solid, remove dead copper, pour order 15): 760,3000 760,1490 1000,1250 1000,1140 1000,0 3000,0 3000,3000
DGND on Bottom Layer "Top Layer-No Net 2" (solid, remove dead copper, pour order 11): 0,1470 500,1470 610,1360 820,1150 820,856.78 820,500 0,500
GNDB on Top Layer "Top Layer-No Net" (solid, remove dead copper, pour order 16): 760,3000 760,1490 1000,1250 1000,1140 1000,0 3000,0 3000,3000
DGND on Top Layer "Top Layer-No Net 2" (solid, remove dead copper, pour order 12): 0,1470 500,1470 610,1360 820,1150 820,856.78 820,500 0,500

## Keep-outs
Keep-Out Layer:
  lines w10: 0,0 3000,0 3000,100 3000,3000 0,3000

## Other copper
Top Layer:
  region net GNDB: 1155,1092 1155,1066 1240,1066 1232,1074 1232,1092
  region net +15VB: 1825,1025 1965,1025 1965,965 1915,915 1870,915 1870,945 1825,990
  region net -15VB: 1825,1095 1870,1140 1870,1165 1920,1165 1960,1125 1960,1055 1825,1055
  region net +15VB: 1386,1145 1396,1145 1396,1172 1404,1180 1404,1202 1464,1262 1367,1262 1367,1219 1386,1200
  region net -15VB: 1367,1150 1376,1150 1376,1167 1379,1170 1379,1194 1353,1220 1353,1261 1236,1261 1236,1212 1247,1201 1333,1201 1367,1167
  region net NetC18_1: 1280,1192 1315,1192 1337,1170 1337,1155 1327,1155 1327,1166 1320,1173 1303,1173 1298,1168 1280,1168
  region net -15VB: 1367,927 1367,902 1329,864 1329,826 1339,826 1376,863 1376,927
  region net NetD3_2: 1751,1061 1752,1060 1787,1060 1787,1092 1856,1161 1856,1203 1751,1203
  region net NetD3_3: 1751,1018 1751,886 1856,886 1856,923 1788,991 1788,1018
  region net -15VB: 915,1689 1049,1555 1193,1555 1193,2370 915,2370
  region net +15VB: 1526,2370 1526,1550 1724,1550 1830,1656 1830,2370
  region net -15VB: 915,1690 915,1592.05 1160,1346.65 1160,1258 1247,1201 1290,1201 1290,1250 1280,1260 1250,1260 1225,1285 1225,1641 1176,1690
  region net +15VB: 1415.24,1260 1460,1260 1480,1280 1480,1625 1528.03,1673 1830,1673 1830,1625.34 1545,1339.41 1545,1292 1470,1217 1416.04,1217
  region net NetD3_3: 1531,1051 1566.5,1051 1575,1042.5 1575,1007.5 1542.5,1040 1532,1040 1531,1041
  region net NetC20_1: 1473,1160 1482,1169 1526,1169 1541,1184 1531,1194 1517,1194 1511,1188 1488,1188 1465,1165 1465,1160
  region net +15VB: 1475,2315 1530,2370 1830,2370 1830,2235 1805,2210 1505,2210 1475,2240
  region net -15VB: 930,2370 1220,2370 1275,2315 1275,2245 1240,2210 980,2210 930,2260
Mid-Layer 2:
  region net -15VB: 1310,1145 1500,1145 1500,935 1310,935
Bottom Layer:
  region net -15VB: 1315,1135 1480,1135 1480,950 1315,950

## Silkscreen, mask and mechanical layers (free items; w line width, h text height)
Top Overlay:
  lines w6: 1320,1346 1320,1350 1335,1365 1335,1412 ; 1366,1413 1366,1367 1383,1350 1383,1345
  lines w25: 0,0 3000,0 3000,3000 0,3000 0,0
  text "DAC8760" at 2160,2558 h60
  text "GND" at 1405,2480 h60 r90
  text "EMC Enhanced EVM" at 1880,2468 h60
  text "+15V" at 1555,2431 h60 r90
  text "-15V" at 1280,2430 h60 r90
  text "2013" at 2350,2068 h40
  text "Texas Instruments" at 1840,1958 h60
  text "V+" at 2355,1280 h40
  text "V-" at 2355,1120 h40
  text "VOUT" at 2505,1110 h60 r90
  text "I-" at 2355,910 h40
  text "I+" at 2355,750 h40
  text "IOUT" at 2505,740 h60 r90
Bottom Overlay:
  the board outline again, w25
Top Solder:
  the board outline again, w25
Bottom Solder:
  the board outline again, w25

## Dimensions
0,3100 to 3000,3100 on Mechanical 1
3100,3000 to 3100,0 on Mechanical 1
